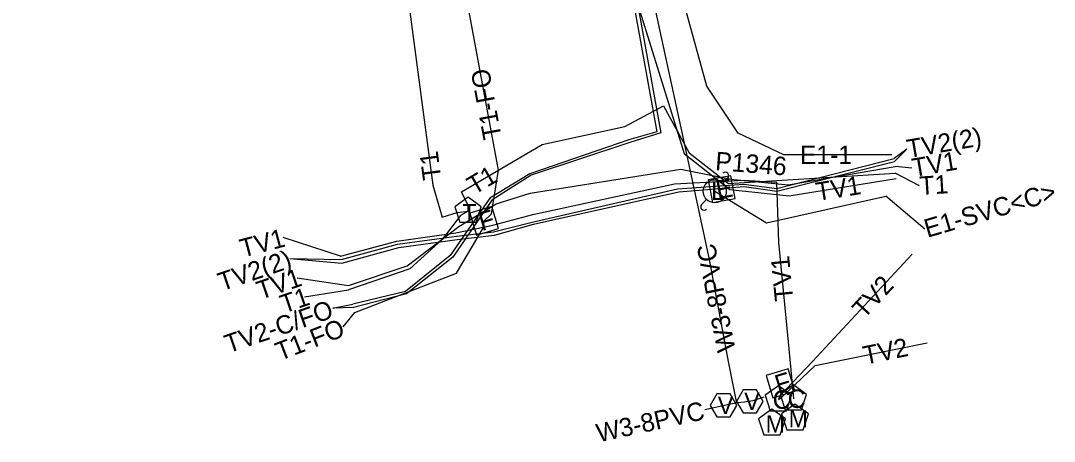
# Model space of a CAD drawing. Extents: x 2336688 to 2352634, y 362473 to 369571.
# Drawn here: x 2347179.1 to 2347403.2, y 367064.3 to 367155.5 of the extents above; entities that cross this region are included whole.
import ezdxf

# ---------------------------------------------------------------- set-up
doc = ezdxf.new("R2010")
doc.units = 0
for name, color, linetype in [('RD_EX_DV_Prop', 7, 'Continuous'), ('RD_EX_DV_TX_Prop', 7, 'Continuous'), ('RD_EX_RW', 7, 'Continuous'), ('RD_EX_RW_TX', 7, 'Continuous'), ('RD_HC_Data_Tic', 7, 'Continuous'), ('RD_PD_CstnLmt', 7, 'Continuous'), ('RD_PD_Final_TrvlWay', 7, 'Continuous'), ('RD_Sketch2', 7, 'Continuous')]:
    doc.layers.add(name, color=color, linetype=linetype)

msp = doc.modelspace()

# ---------------------------------------------------------------- linework, layer by layer
at = {"layer": 'RD_EX_DV_Prop'}
msp.add_line((2347375.07, 367110.35), (2347366.67, 367117.45), dxfattribs=at)
at = {"layer": 'RD_EX_RW'}
for p, q in [((2347371.17, 367127.68), (2347368.44, 367125.66)), ((2347371.17, 367127.68), (2347368.55, 367125.01)), ((2347372.31, 367123.58), (2347368.69, 367123.91)), ((2347373.93, 367119.72), (2347368.66, 367122.48)), ((2347248.4, 367104.47), (2347235.99, 367108.51)), ((2347237.45, 367103.99), (2347248.64, 367103.74)), ((2347237.45, 367103.99), (2347248.67, 367102.93)), ((2347238.99, 367099.8), (2347250.15, 367098.14)), ((2347240.62, 367095.66), (2347250.15, 367097.15)), ((2347246.74, 367093.22), (2347251.09, 367094.03)), ((2347251.22, 367093.33), (2347246.74, 367093.22)), ((2347249, 367089.16), (2347251.53, 367092.27))]:
    msp.add_line(p, q, dxfattribs=at)
at = {"layer": 'RD_EX_RW_TX'}
for points in [[(2347334.55, 367298.63), (2347331.8, 367296.93), (2347301.27, 367287.43), (2347283.36, 367284.15), (2347283.95, 367275.18), (2347289.35, 367262.51), (2347299.08, 367226.8), (2347308.57, 367177.85), (2347317.02, 367131.39), (2347310.94, 367129.7), (2347289.46, 367122.33), (2347280.81, 367117.06), (2347272.21, 367104.58), (2347262.49, 367096.82), (2347251.09, 367094.03)], [(2347334.55, 367298.63), (2347331.8, 367296.53), (2347302.45, 367287.2), (2347283.9, 367283.67), (2347284.61, 367275.35), (2347289.93, 367262.7), (2347299.68, 367227.09), (2347309.43, 367178.07), (2347317.83, 367131.2), (2347311.13, 367129.12), (2347289.71, 367122), (2347281.24, 367116.62), (2347272.75, 367104.22), (2347262.7, 367096.28), (2347251.22, 367093.33)], [(2347334.55, 367298.63), (2347331.8, 367296.73), (2347301.31, 367295.65), (2347287.81, 367289.55), (2347286.17, 367275.46), (2347297.32, 367226.43), (2347307.12, 367177.6), (2347322.94, 367126.73), (2347332.85, 367118.93), (2347345.67, 367117.58), (2347368.91, 367121.3)], [(2347251.53, 367092.27), (2347273.58, 367100.79), (2347279.31, 367110.51), (2347279.56, 367112.12), (2347281.17, 367113.65), (2347282.65, 367123.08), (2347274.25, 367168.45), (2347264.71, 367218.53), (2347254.72, 367267.34), (2347249.12, 367285.21), (2347244.59, 367290.99), (2347234.99, 367291.06), (2347216.14, 367291.34), (2347184.08, 367281.81), (2347138.56, 367267.72)], [(2347148.27, 367240), (2347194.65, 367253.63), (2347238.25, 367267.08), (2347241.57, 367265.57), (2347262.35, 367165.72), (2347268.45, 367119.85), (2347270.43, 367112.95), (2347273.7, 367113.96), (2347276.05, 367114.24), (2347274.41, 367113.29), (2347270.48, 367108.09), (2347263.45, 367101.7), (2347250.15, 367097.15)], [(2347276.05, 367114.24), (2347276.05, 367115.48), (2347274.66, 367118.38), (2347292.12, 367128.66), (2347310.02, 367132.61), (2347318.4, 367137.08), (2347323.98, 367126.89), (2347332.52, 367120.21), (2347368.66, 367122.48)], [(2347248.64, 367103.74), (2347260.79, 367107.07), (2347273.56, 367108.82), (2347281.55, 367109.72), (2347290.25, 367111.94), (2347321.47, 367119.06), (2347335.87, 367120.09), (2347343.03, 367119.16), (2347368.44, 367125.66)], [(2347248.67, 367102.93), (2347261.04, 367106.35), (2347273.69, 367108.07), (2347281.81, 367109.01), (2347290.26, 367111.43), (2347321.73, 367118.44), (2347335.93, 367119.56), (2347342.99, 367118.57), (2347368.55, 367125.01)], [(2347250.15, 367098.14), (2347262.86, 367102.39), (2347274.08, 367110.87), (2347282.17, 367115.84), (2347289.52, 367118.15), (2347322.17, 367123.3), (2347333, 367121.16), (2347345.45, 367119.94), (2347368.69, 367123.91)], [(2347248.4, 367104.47), (2347260.65, 367107.71), (2347273.44, 367109.51), (2347281.41, 367111.22), (2347290.07, 367113.49), (2347320.82, 367120.13), (2347335.91, 367120.95), (2347342.96, 367120.51), (2347343.38, 367107.42), (2347345.45, 367085.9), (2347346.57, 367074.4), (2347346.6, 367073.55)], [(2347372.32, 367104.87), (2347350.75, 367081.59), (2347343.63, 367074.2), (2347343.35, 367073.37), (2347344.05, 367073.82), (2347351.33, 367080.74), (2347375.61, 367085.7)]]:
    msp.add_lwpolyline(points, dxfattribs=at)
for points in [[(2347276.05, 367117.24), (2347273.2, 367115.17), (2347274.29, 367111.81), (2347277.81, 367111.81), (2347278.9, 367115.17)], [(2347281.22, 367115.24), (2347276.44, 367113.78), (2347277.9, 367108.99), (2347282.68, 367110.45)], [(2347345.47, 367080.02), (2347340.69, 367078.56), (2347342.14, 367073.78), (2347346.93, 367075.23)], [(2347343.35, 367076.37), (2347340.5, 367074.3), (2347341.59, 367070.94), (2347345.11, 367070.94), (2347346.2, 367074.3)], [(2347346.6, 367076.55), (2347343.75, 367074.48), (2347344.84, 367071.12), (2347348.36, 367071.12), (2347349.45, 367074.48)]]:
    msp.add_lwpolyline(points, close=True, dxfattribs=at)
at = {"layer": 'RD_HC_Data_Tic'}
for p, q in [((2347331.32, 367120.31), (2347332.38, 367121.37)), ((2347326.72, 367115.71), (2347327.78, 367116.77))]:
    msp.add_line(p, q, dxfattribs=at)
msp.add_circle((2347329.55, 367118.54), 2.5, dxfattribs=at)
for centre, start, end in [((2347331.85, 367121.9), 315, 135), ((2347327.25, 367115.18), 135, 315)]:
    msp.add_arc(centre, 0.75, start, end, dxfattribs=at)
at = {"layer": 'RD_PD_Final_TrvlWay'}
for points in [[(2347367.97, 367126.47), (2347344.52, 367126.44), (2347334.62, 367131.11), (2347327.84, 367141.36), (2347317.23, 367179.92), (2347305.06, 367228.1), (2347294.65, 367280.06), (2347301.58, 367294.16), (2347331.76, 367300.13), (2347334.55, 367298.63)], [(2347329.55, 367118.54), (2347340.74, 367111.68), (2347366.67, 367117.45)]]:
    msp.add_lwpolyline(points, dxfattribs=at)
msp.add_lwpolyline([(2347333.03, 367121.91), (2347328.12, 367120.99), (2347329.04, 367116.08), (2347333.95, 367117)], close=True, dxfattribs=at)
at = {"layer": 'RD_Sketch2'}
for points in [[(2347334.3, 367072.61), (2347332.51, 367081.63), (2347328.41, 367103.77), (2347322.65, 367130.6), (2347312.24, 367178.63), (2347303.42, 367220.52), (2347290.42, 367277.78), (2347284.28, 367304.45), (2347284.15, 367304.81), (2347283.51, 367309.44)], [(2347340.19, 367073.89), (2347337.79, 367073.07), (2347335.99, 367072.8), (2347334.5, 367072.65), (2347332.65, 367072.28), (2347327.39, 367071.14)]]:
    msp.add_lwpolyline(points, dxfattribs=at)
for points in [[(2347334.31, 367072.11), (2347332.87, 367074.6), (2347329.98, 367074.6), (2347328.54, 367072.11), (2347329.98, 367069.61), (2347332.87, 367069.61)], [(2347340.05, 367072.96), (2347338.6, 367075.46), (2347335.72, 367075.46), (2347334.27, 367072.96), (2347335.72, 367070.46), (2347338.6, 367070.46)], [(2347341.95, 367071.27), (2347339.05, 367069.16), (2347340.16, 367065.75), (2347343.74, 367065.75), (2347344.85, 367069.16)], [(2347346.94, 367072.36), (2347344.04, 367070.25), (2347345.15, 367066.84), (2347348.73, 367066.84), (2347349.84, 367070.25)]]:
    msp.add_lwpolyline(points, close=True, dxfattribs=at)

# ---------------------------------------------------------------- texts
at = {"layer": 'RD_EX_DV_Prop'}
for s, rotation, p in [('E1-1', 0.0831, (2347348.01, 367124.44)), ('E1-SVC<C>', 16.3721, (2347375.64, 367108.43))]:
    msp.add_text(s, height=4, rotation=rotation, dxfattribs=at).set_placement(p)
at = {"layer": 'RD_EX_DV_TX_Prop'}
msp.add_text('P1346', height=4, rotation=355.5315, dxfattribs=at).set_placement((2347329.55, 367123.15))
at = {"layer": 'RD_EX_RW'}
for s, rotation, p in [('T1-FO', 100.489, (2347283.37, 367130.18)), ('TV2(2)', 9.6881, (2347371.54, 367125.72)), ('T1', 97.5715, (2347270.28, 367121.25)), ('TV1', 9.6881, (2347372.68, 367121.62)), ('T1', 30.4579, (2347277.38, 367117.67)), ('TV1', 9.0849, (2347351.79, 367116.41)), ('T1', 3.599, (2347374.06, 367117.73)), ('TV1', 14.7919, (2347227.2, 367104.13)), ('TV2(2)', 18.872, (2347222.69, 367096.83)), ('TV1', 95.4867, (2347346.59, 367094.93)), ('TV1', 18.872, (2347231.07, 367094.98)), ('TV2', 47.1733, (2347361.94, 367090.73)), ('T1', 18.872, (2347236.14, 367092.01)), ('TV2-C/FO', 18.872, (2347224.1, 367083.37)), ('T1-FO', 21.1263, (2347235.26, 367081.71)), ('TV2', 11.5648, (2347362.14, 367080.91))]:
    msp.add_text(s, height=4, rotation=rotation, dxfattribs=at).set_placement(p)
at = {"layer": 'RD_EX_RW_TX'}
for s, height, p in [('T', 3.75, (2347274.82, 367112.01)), ('C', 4, (2347345.37, 367071.55)), ('C', 4, (2347342.12, 367071.37))]:
    msp.add_text(s, height=height, dxfattribs=at).set_placement(p)
for p in [(2347279.06, 367109.87), (2347343.31, 367074.65)]:
    msp.add_text('F', height=4, rotation=16.9682, dxfattribs=at).set_placement(p)
at = {"layer": 'RD_HC_Data_Tic'}
msp.add_text('L', height=4, rotation=360, dxfattribs=at).set_placement((2347328.74, 367116.61))
at = {"layer": 'RD_PD_CstnLmt'}
for rotation, p in [(101.0197, (2347334.09, 367084.11)), (12.2738, (2347304.37, 367064.08))]:
    msp.add_text('W3-8PVC', height=4, rotation=rotation, dxfattribs=at).set_placement(p)
at = {"layer": 'RD_PD_Final_TrvlWay'}
msp.add_text('E', height=4, rotation=10.6261, dxfattribs=at).set_placement((2347330.21, 367116.8))
at = {"layer": 'RD_Sketch2'}
for s, p in [('V', (2347330.21, 367070.23)), ('V', (2347335.95, 367071.09)), ('M', (2347345.57, 367067.32)), ('M', (2347340.58, 367066.23))]:
    msp.add_text(s, height=3.75, dxfattribs=at).set_placement(p)

doc.saveas('drawing.dxf')
